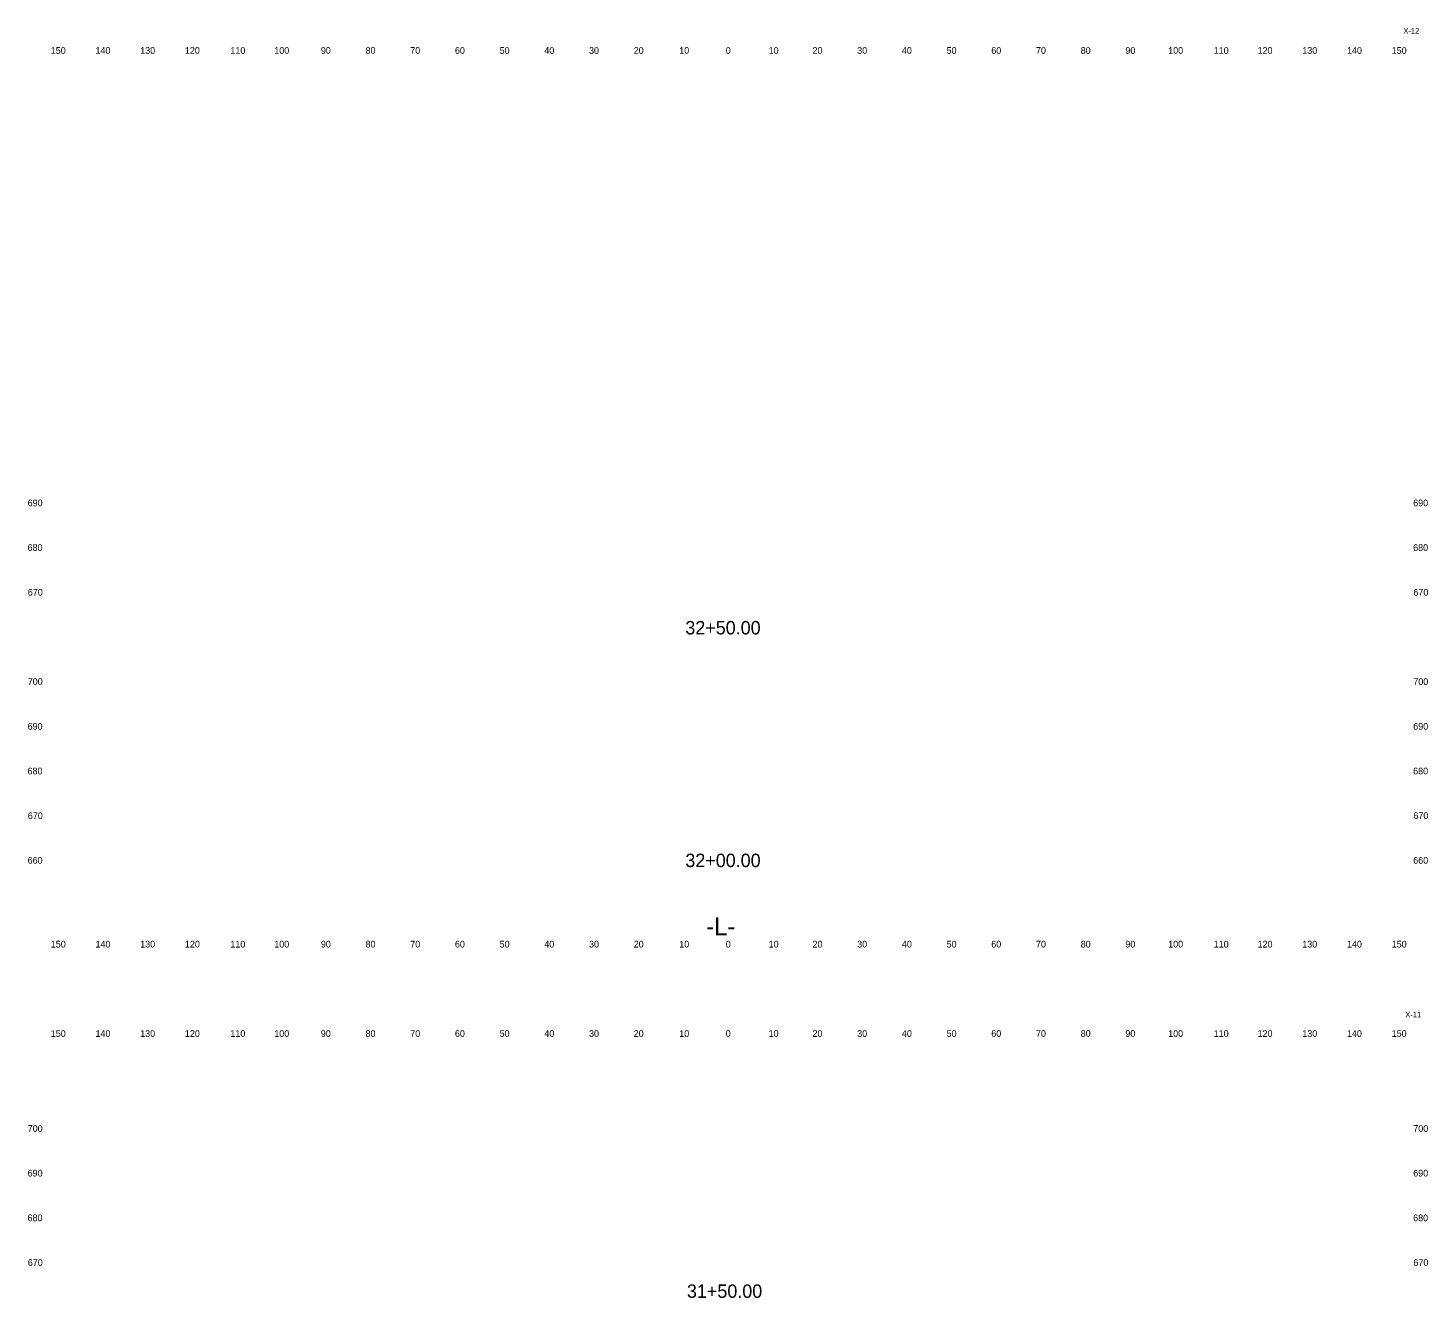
# Model space of a CAD drawing. Extents: x 3 to 317, y 0 to 2407.
# Drawn here: x 3.3 to 316.6, y 2122.8 to 2407 of the extents above; entities that cross this region are included whole.
import ezdxf

# ---------------------------------------------------------------- set-up
doc = ezdxf.new("R2010")
doc.units = 0
for name, color, linetype in [('Prop XS Ditch Standard Text', 7, 'Continuous'), ('Prop XS Dump Level', 7, 'Continuous'), ('Prop XS SE Text', 7, 'Continuous'), ('Prop XS Sheet Number', 7, 'Continuous'), ('Prop XS SS Elevation Text', 7, 'Continuous')]:
    doc.layers.add(name, color=color, linetype=linetype)

msp = doc.modelspace()

# ---------------------------------------------------------------- texts
at = {"layer": 'Prop XS Ditch Standard Text'}
for s, p in [('32+50.00', (150.41, 2271.32)), ('32+00.00', (150.41, 2219.25)), ('31+50.00', (150.77, 2122.85))]:
    msp.add_text(s, height=3, dxfattribs=at).set_placement(p)
at = {"layer": 'Prop XS Dump Level'}
for s, p in [('150', (8.44, 2401.25)), ('140', (18.44, 2401.25)), ('130', (28.44, 2401.25)), ('120', (38.44, 2401.25)), ('110', (48.62, 2401.25)), ('100', (58.44, 2401.25)), ('90', (68.86, 2401.25)), ('80', (78.86, 2401.25)), ('70', (88.86, 2401.25)), ('60', (98.86, 2401.25)), ('50', (108.86, 2401.25)), ('40', (118.86, 2401.25)), ('30', (128.86, 2401.25)), ('20', (138.86, 2401.25)), ('10', (149.04, 2401.25)), ('0', (159.45, 2401.25)), ('10', (169.04, 2401.25)), ('20', (178.86, 2401.25)), ('30', (188.86, 2401.25)), ('40', (198.86, 2401.25)), ('50', (208.86, 2401.25)), ('60', (218.86, 2401.25)), ('70', (228.86, 2401.25)), ('80', (238.86, 2401.25)), ('90', (248.86, 2401.25)), ('100', (258.44, 2401.25)), ('110', (268.62, 2401.25)), ('120', (278.44, 2401.25)), ('130', (288.44, 2401.25)), ('140', (298.44, 2401.25)), ('150', (308.44, 2401.25)), ('150', (8.44, 2201.25)), ('140', (18.44, 2201.25)), ('130', (28.44, 2201.25)), ('120', (38.44, 2201.25)), ('110', (48.62, 2201.25)), ('100', (58.44, 2201.25)), ('90', (68.86, 2201.25)), ('80', (78.86, 2201.25)), ('70', (88.86, 2201.25)), ('60', (98.86, 2201.25)), ('50', (108.86, 2201.25)), ('40', (118.86, 2201.25)), ('30', (128.86, 2201.25)), ('20', (138.86, 2201.25)), ('10', (149.04, 2201.25)), ('0', (159.45, 2201.25)), ('10', (169.04, 2201.25)), ('20', (178.86, 2201.25)), ('30', (188.86, 2201.25)), ('40', (198.86, 2201.25)), ('50', (208.86, 2201.25)), ('60', (218.86, 2201.25)), ('70', (228.86, 2201.25)), ('80', (238.86, 2201.25)), ('90', (248.86, 2201.25)), ('100', (258.44, 2201.25)), ('110', (268.62, 2201.25)), ('120', (278.44, 2201.25)), ('130', (288.44, 2201.25)), ('140', (298.44, 2201.25)), ('150', (308.44, 2201.25)), ('150', (8.44, 2181.25)), ('140', (18.44, 2181.25)), ('130', (28.44, 2181.25)), ('120', (38.44, 2181.25)), ('110', (48.62, 2181.25)), ('100', (58.44, 2181.25)), ('90', (68.86, 2181.25)), ('80', (78.86, 2181.25)), ('70', (88.86, 2181.25)), ('60', (98.86, 2181.25)), ('50', (108.86, 2181.25)), ('40', (118.86, 2181.25)), ('30', (128.86, 2181.25)), ('20', (138.86, 2181.25)), ('10', (149.04, 2181.25)), ('0', (159.45, 2181.25)), ('10', (169.04, 2181.25)), ('20', (178.86, 2181.25)), ('30', (188.86, 2181.25)), ('40', (198.86, 2181.25)), ('50', (208.86, 2181.25)), ('60', (218.86, 2181.25)), ('70', (228.86, 2181.25)), ('80', (238.86, 2181.25)), ('90', (248.86, 2181.25)), ('100', (258.44, 2181.25)), ('110', (268.62, 2181.25)), ('120', (278.44, 2181.25)), ('130', (288.44, 2181.25)), ('140', (298.44, 2181.25)), ('150', (308.44, 2181.25))]:
    msp.add_text(s, height=1.5, dxfattribs=at).set_placement(p)
at = {"layer": 'Prop XS SE Text'}
for s, p in [('690', (3.26, 2300)), ('690', (313.26, 2300)), ('680', (3.24, 2290)), ('680', (313.24, 2290)), ('670', (3.3, 2280)), ('670', (313.3, 2280)), ('700', (3.28, 2260)), ('700', (313.28, 2260)), ('690', (3.26, 2250)), ('690', (313.26, 2250)), ('680', (3.24, 2240)), ('680', (313.24, 2240)), ('670', (3.3, 2230)), ('670', (313.3, 2230)), ('660', (3.26, 2220)), ('660', (313.26, 2220)), ('700', (3.28, 2160)), ('700', (313.28, 2160)), ('690', (3.26, 2150)), ('690', (313.26, 2150)), ('680', (3.24, 2140)), ('680', (313.24, 2140)), ('670', (3.3, 2130)), ('670', (313.3, 2130))]:
    msp.add_text(s, height=1.5, dxfattribs=at).set_placement(p)
at = {"layer": 'Prop XS Sheet Number'}
for s, p in [('X-12', (311.07, 2405.76)), ('X-11', (311.5, 2185.61))]:
    msp.add_text(s, height=1.25, dxfattribs=at).set_placement(p)
at = {"layer": 'Prop XS SS Elevation Text'}
msp.add_text('-L-', height=4, dxfattribs=at).set_placement((155.06, 2204))

doc.saveas('drawing.dxf')
